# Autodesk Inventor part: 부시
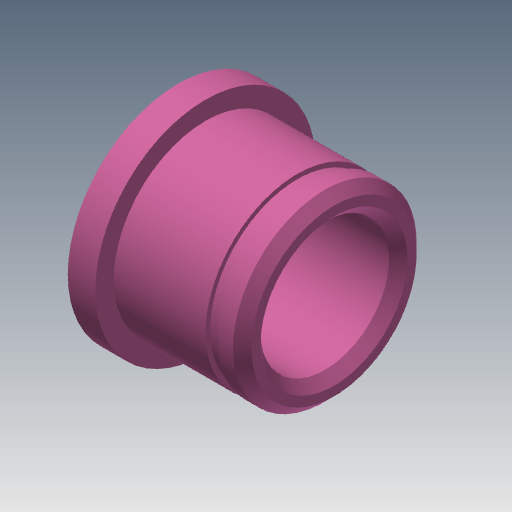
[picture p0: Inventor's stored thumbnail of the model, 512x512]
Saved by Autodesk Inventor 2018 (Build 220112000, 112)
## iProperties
Created: 2019-01
Part Number: 부시
Material: 강철, 연강
Document SubType Name: Modeling
Designer: mduedu
Density: 7.86 g/cm^3
Appearance: 분홍색
Mass: 23.9234 g
Surface Area: 24.4489 cm^2
Volume: 3.04369 cm^3
Author: mduedu
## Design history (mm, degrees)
sketch "스케치1"
  geometry: L1 (0, 0)-(3, 0); L2 (3, 0)-(3, 12); L3 (3, 12)-(0, 12); L4 (0, 12)-(0, 0); L5 (3, 0)-(17, 0); L6 (17, 0)-(17, 10); L7 (17, 10)-(3, 10); L8 (3, 10)-(3, 0)
  constraints: 16 end point, 4 parallel, 2 horizontal, 2 perpendicular
  dimensions: "d0" = 17 distance between parallel lines of L6 L4; "d2" = 3 distance of L2.end L3.end; "d3" = 24 diameter of L3 L1; "d4" = 20 diameter of L7 L5
revolve "회전1" sketch "스케치1" stored, may be unused: angle "d5" = 90 deg
sketch "스케치2"
  geometry: C1 r 7 at (0, 0); 1 further point
  constraints: 1 centre point, 1 coincident
  dimensions: "d6" = 14 diameter of C1
extrude "돌출1" cut sketch "스케치2" extent not by distance; stored distance "d7" = 10; taper "d8" = 0 deg
chamfer "모따기1" distance "d9" = 1; stored, may be unused: second distance "d10" = 2, angle "d11" = 45 deg
node "작업 평면1"
sketch "스케치3"
  geometry: C1 r 9.5 at (0, 0); C2 r 10 at (0, 0) reference; 1 further point
  constraints: 1 centre point, 1 coincident
  dimensions: "d13" = 19 diameter of C1
extrude "돌출2" cut sketch "스케치3" distance "d14" = 1.35; taper "d15" = 0 deg
node "솔리드1"
